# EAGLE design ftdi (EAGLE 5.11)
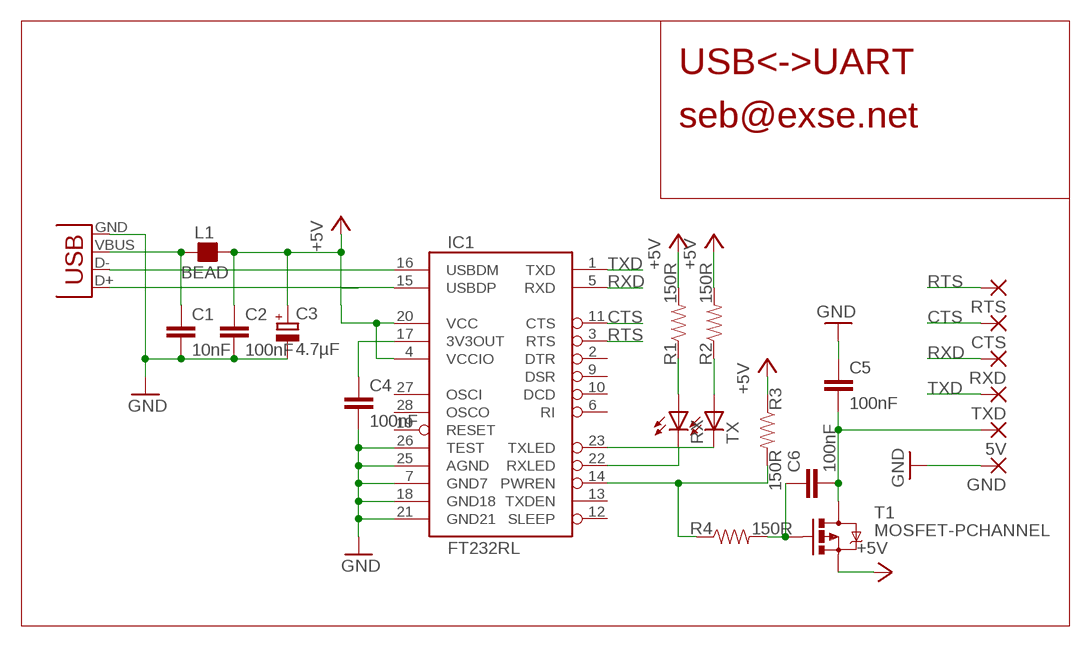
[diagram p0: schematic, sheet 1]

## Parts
5V  SMD2  [SMD1,27-2,54]
C1  10nF  CAP0805  [0805]
C2  100nF  CAP0805  [0805]
C3  4.7µF  CPOL-EUSMCC  [SMC_C]
C4  100nF  CAP0805  [0805]
C5  100nF  CAP0805  [0805]
C6  100nF  CAP0805  [0805]
CTS  SMD2  [SMD1,27-2,54]
GND  SMD2  [SMD1,27-2,54]
IC1  FT232RL  FT232RLSSOP  [SSOP28DB]
L1  BEAD  FB_0805  [L0805]
R1  150R  RESISTOR  [0805]
R2  150R  RESISTOR  [0805]
R3  150R  RESISTOR  [0805]
R4  150R  RESISTOR  [0805]
RTS  SMD2  [SMD1,27-2,54]
RX  LEDCHIP-LED0805  [CHIP-LED0805]
RXD  SMD2  [SMD1,27-2,54]
T1  MOSFET-PCHANNEL  [SOT23]
TX  LEDCHIP-LED0805  [CHIP-LED0805]
TXD  SMD2  [SMD1,27-2,54]
X1  USB-SMD-NS  [USB-MINIB-NOSTOP]

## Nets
+5V: C2.1 C3.+ IC1.4(VCCIO) IC1.20(VCC) L1.2 R1.2 R2.2 R3.1 T1.2(S)
CTS: CTS.1(P) IC1.11(CTS)
GND: C1.2 C2.2 C3.- C4.2 C5.1 GND.1(P) IC1.7(GND7) IC1.18(GND18) IC1.21(GND21) IC1.25(AGND) IC1.26(TEST) X1.GND
N$1: IC1.16(USBDM) X1.D-
N$2: IC1.15(USBDP) X1.D+
N$4: C1.1 L1.1 X1.VBUS
N$5: IC1.14(PWREN) R3.2 R4.1
N$6: 5V.1(P) C5.2 C6.2 T1.3(D)
N$7: C6.1 R4.2 T1.1(G)
N$19: R1.1 RX.A
N$20: R2.1 TX.A
N$27: IC1.22(RXLED) RX.C
N$28: IC1.23(TXLED) TX.C
N$29: C4.1 IC1.17(3V3OUT)
RTS: IC1.3(RTS) RTS.1(P)
RXD: IC1.5(RXD) RXD.1(P)
TXD: IC1.1(TXD) TXD.1(P)
Unconnected: IC1.2(DTR) IC1.6(RI) IC1.9(DSR) IC1.10(DCD) IC1.12(SLEEP) IC1.13(TXDEN) IC1.19(RESET) IC1.27(OSCI) IC1.28(OSCO)

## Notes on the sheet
- USB<->UART
- seb@exse.net

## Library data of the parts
5V CTS GND RTS RXD TXD = wirepad:SMD2: SMD PAD
C1 C2 C4-C6 = SparkFun:CAP: Capacitor
C3 = resistor:CPOL-EU: POLARIZED CAPACITOR, European symbol
IC1 = SparkFun:FT232RL: USB UART FT232RL 4th Generation USB UART (USB <-> Serial) Controller. Spark Fun Electronics SKU : COM-00650
L1 = rc-master-smd:FB_: FERRITE BEAD
R1-R4 = SparkFun:RESISTOR: Resistor
RX TX = led:LED: LED
T1 = SparkFun:MOSFET-PCHANNEL
X1 = SparkFun:USB: USB Connectors USB-B-PTH is fully proven SKU : PRT-00139 USB-miniB is fully proven SKU : PRT-00587 USB-A-PCB is untested. USB-A-H is throughly reviewed, but untested. Spark Fun Electronics SKU : PRT-00437 USB-B-SMT is throughly reviewed, but untested. Needs silkscreen touching up. USB-A-S has not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

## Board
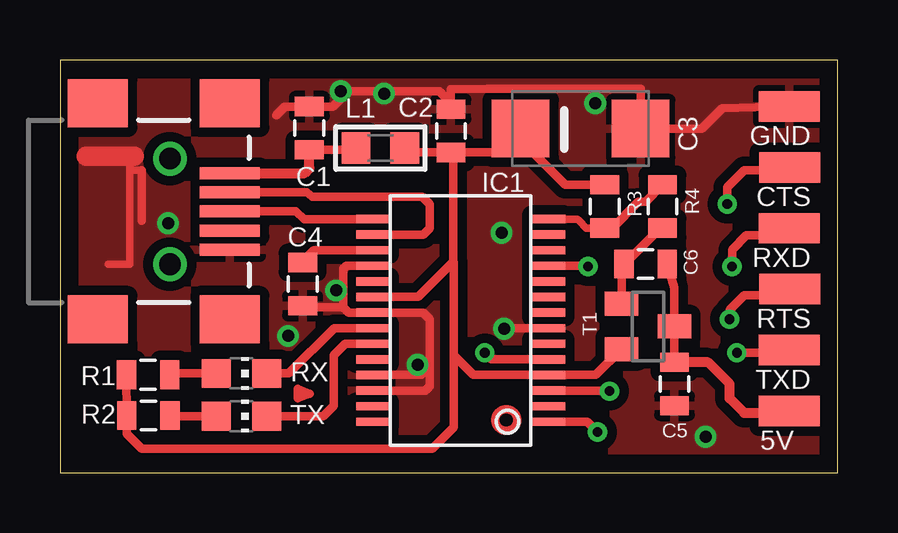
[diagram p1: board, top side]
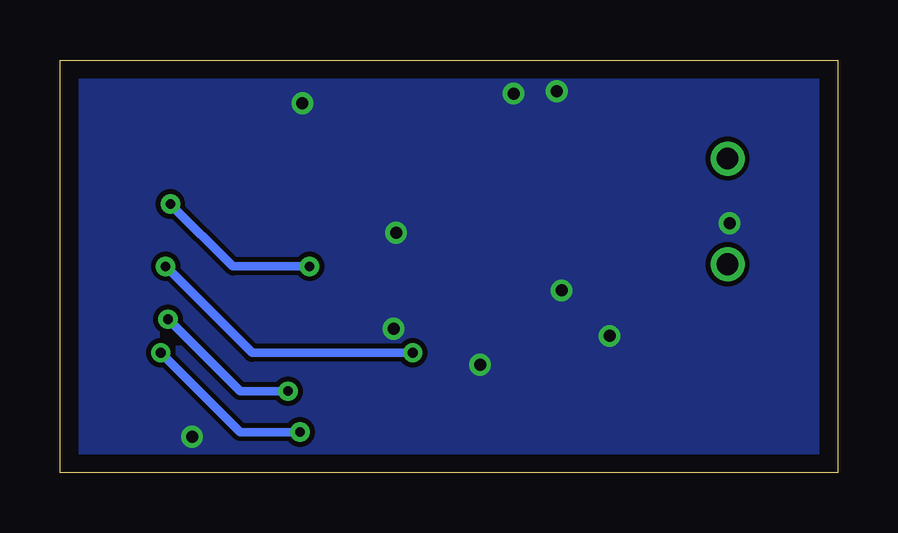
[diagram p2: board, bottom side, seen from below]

Size 32.4 x 17.2 mm. Coordinates in mm from the lower left corner, seen from the top.
Outline: 0,0 32.4,0 32.4,17.2 0,17.2 0,0
Copper layers (1*16): Top 0.035mm / dielectric 1.5mm / Bottom 0.035mm
Design rules "default *": minimum track width 10mil, minimum drill 0.3mm, track to track 8mil, track to pad 8mil, pad to pad 8mil, via to via 8mil, smd to smd 8mil, copper to edge 30mil, drill to drill 8mil, minimum pad ring 10mil, minimum via ring 8mil, stop-mask expansion 4mil, vias tented up to drill 50mil, thermal gap 10mil
tRestrict: 1 lines

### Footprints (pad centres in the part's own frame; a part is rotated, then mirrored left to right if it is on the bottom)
SMD1,27-2,54 = smd 1.27 x 2.54: 1 0,0
0805 = smd 0.8 x 1.2: 1 -0.9,0; 2 0.9,0
SMC_C = smd 2.4 x 2.4: + -2.5,0; - 2.5,0
SSOP28DB = smd 0.348 x 1.397: 1 -4.225,-3.656; 2 -3.575,-3.656; 3 -2.925,-3.656; 4 -2.275,-3.656; 5 -1.625,-3.656; 6 -0.975,-3.656; 7 -0.325,-3.656; 8 0.325,-3.656; 9 0.975,-3.656; 10 1.625,-3.656; 11 2.275,-3.656; 12 2.925,-3.656; 13 3.575,-3.656; 14 4.225,-3.656; 15 4.225,3.656; 16 3.575,3.656; 17 2.925,3.656; 18 2.275,3.656; 19 1.625,3.656; 20 0.975,3.656; 21 0.325,3.656; 22 -0.325,3.656; 23 -0.975,3.656; 24 -1.625,3.656; 25 -2.275,3.656; 26 -2.925,3.656; 27 -3.575,3.656; 28 -4.225,3.656
L0805 = smd 1.2 x 1.3: 1 -1.016,0; 2 1.016,0
CHIP-LED0805 = smd 1.2 x 1.2: A 0,-1.05; C 0,1.05
SOT23 = smd 1 x 1.4: 1 -0.95,-1.1; 2 0.95,-1.1; 3 0,1.1
USB-MINIB-NOSTOP = smd 2.5 x 0.5: D+ 2.5,0; D- 2.5,0.8; GND 2.5,-1.6; ID 2.5,-0.8; VBUS 2.5,1.6 | smd 2.5 x 2: G1 -3,-4.5; G2 -3,4.5; G3 2.5,4.5; G4 2.5,-4.5 | drill 0.9 pad 0.8 round: H1 0,2.2 | drill 0.9 pad 0.787 round: H2 0,-2.2

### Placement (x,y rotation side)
5V  30.39,2.57 90 top
C1  10.39,14.36 90 top
C2  16.29,14.25 90 top
C3  21.69,14.34 0 top
C4  10.11,7.86 270 top
C5  25.6,3.7 90 top
C6  24.4,8.7 0 top
CTS  30.4,12.73 90 top
GND  30.39,15.27 90 top
IC1  16.69,6.35 90 top
L1  13.35,13.53 0 top
R1  3.67,4.09 180 top
R2  3.68,2.39 180 top
R3  22.7,11.1 270 top
R4  25.1,11.1 270 top
RTS  30.4,7.65 90 top
RX  7.56,4.14 270 top
RXD  30.39,10.19 90 top
T1  24.5,6.1 270 top
TX  7.56,2.36 270 top
TXD  30.39,5.11 90 top
X1  4.58,10.89 0 top

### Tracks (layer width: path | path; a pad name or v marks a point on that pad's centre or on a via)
+5V
  Top 0.35: IC1.20 14.93,7.33 16.39,8.79 | R1.2 R2.2 2.78,1.62 3.4,1 15.5,1 16.4,1.9 | C3.+ 20.2,14.25 20.2,13.4 20.15,13.35 19.7,13.35 | 16.4,1.9 16.39,1.91 | C2.1 14.45,13.35 L1.2 | C2.1 19.7,13.35 | 16.39,8.79 16.39,13.25 C2.1 | R3.1 21.05,12 19.7,13.35 | T1.2 22.32,4.08 IC1.4 17.23,4.08 16.4,4.9 | 16.4,4.9 16.4,5.4 16.4,8.78 16.39,8.79 | 16.4,1.9 16.4,4.9
  Top 0.406: L1.2 14.37,13.43 | 19.64,14.34 C3.+ 19.73,13.8
CTS  (via drill 0.4)
  Top 0.35: IC1.11 21.98,8.62 v22,8.6 | v27.8,11.2 27.8,11.9 28.5,12.6 30.3,12.6 CTS.1
  Bottom 0.35: v22,8.6 25.2,8.6 v27.8,11.2
GND  (via drill 0.5)
  Top 0.305: 2.9,12.6 3.4,12.6 | 2.9,12.6 2.9,13.2 | 2,8.7 2.9,8.7 2.9,12.6
  Top 0.35: IC1.26 15.22,3.43 15.4,3.6 15.4,4.4 | 15.4,4.4 15.4,6.4 15.12,6.68 IC1.21 12.03,6.68 11.8,6.9 | IC1.25 15.07,4.08 15.4,4.4 | 11.8,6.9 11.8,8.5 11.93,8.62 IC1.18 | 11.8,6.9 10.26,6.9 C4.2 10.22,6.96 | 9,14.9 9.36,15.26 C1.2 11.36,15.26 12,15.9 15.8,15.9 16.55,15.15 C2.2 16.29,15.99 17.8,16 24.2,16 24.19,15.91 C3.- 26.74,14.34 27.6,15.2 GND.1 | 3.4,12.6 3.4,10.5 | IC1.7 18.52,6.03 v18.5,6
  Top 0.813: 1.1,13.2 2.9,13.2 3.1,13.2
  other vias: 9.5,5.7 11.5,7.6 14.9,4.5 18.4,10 22.3,15.4 13.5,15.8 11.7,15.9 4.5,10.4 26.9,1.5
  pour Top (isolate 0.4): 0,0 34.8,0 34.8,17.2 0,17.2
  pour Bottom: 33.6,17.2 0,17.2 0,0 33.6,0
N$1
  Top 0.35: IC1.16 15.12,9.93 15.4,10.2 15.4,11.2 15.1,11.5 10.5,11.5 10.29,11.69 X1.D-
N$2
  Top 0.35: X1.D+ 9.81,10.89 10.18,10.57 IC1.15
N$3
  Top 0.35: 9.9,3.5 9.9,3.1 10.4,3.3 9.9,3.5
N$4
  Top 0.35: C1.1 12.36,13.46 L1.1
  Top 0.406: X1.VBUS 10.19,12.49 10.39,12.69 C1.1 | L1.1 12.33,13.43
N$5
  Top 0.305: R3.2 21.93,10.2 21.64,10.49 21.56,10.57 IC1.14
  Top 0.35: R3.2 23,10.2 24.1,11.3 24.4,11.3 R4.1
N$6
  Top 0.35: C6.2 25.6,7.7 T1.3 C5.2
  Top 0.406: C5.2 27,4.6 27.9,3.7 27.9,3.1 28.5,2.5 30.31,2.5 5V.1
N$7
  Top 0.35: T1.1 23.4,8.1 C6.1 25,10.2 R4.2
N$19
  Top 0.35: R1.1 4.72,4.14 RX.A
N$20
  Top 0.35: R2.1 4.71,2.36 TX.A
N$27
  Top 0.35: RX.C 9.53,4.14 11.43,6.03 IC1.22
N$28
  Top 0.35: IC1.23 11.88,5.38 11.4,4.9 11.4,2.8 10.96,2.36 TX.C
N$29
  Top 0.35: C4.1 10.06,8.76 10.57,9.28 IC1.17
RTS  (via drill 0.4)
  Top 0.35: IC1.3 22.88,3.43 v22.9,3.4 | v27.9,6.4 27.9,6.8 28.5,7.4 30.2,7.4 RTS.1
  Bottom 0.35: v22.9,3.4 24.9,3.4 v27.9,6.4
RXD  (via drill 0.4)
  Top 0.35: IC1.5 17.98,4.73 v17.7,5 | v28,8.6 28,9.3 28.6,9.9 30.25,9.9 RXD.1
  Bottom 0.35: v17.7,5 24.4,5 v28,8.6
TXD  (via drill 0.4)
  Top 0.35: 30.65,4.8 TXD.1 30.33,5 v28.2,5 | v22.4,1.7 21.98,2.12 IC1.1
  Bottom 0.35: v22.4,1.7 24.9,1.7 v28.2,5
(copper drawn outside any net)
  shapes: Top circle x1

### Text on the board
bStop: GND | seb@exse.net | RX | TX | 5V | UART <-> USB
